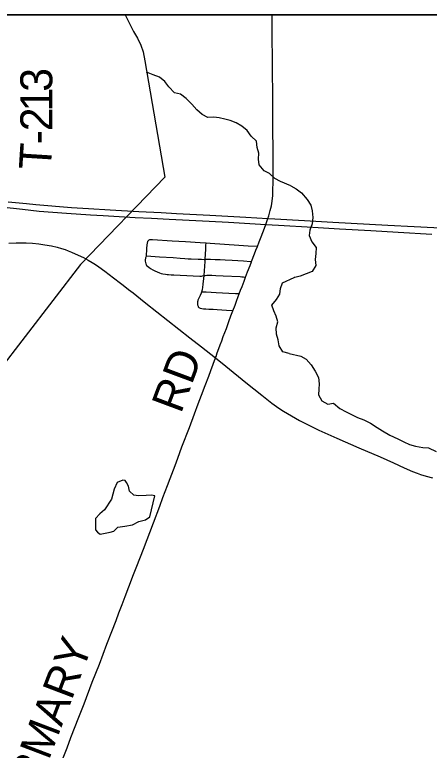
# Model space of a CAD drawing. Extents: x 0 to 34, y 0 to 22.
# Drawn here: x 7.094 to 7.83, y 19.311 to 20.617 of the extents above; entities that cross this region are included whole.
import ezdxf

# ---------------------------------------------------------------- set-up
doc = ezdxf.new("R2010")
doc.units = 0
for name, color, linetype in [('GM_X_Corporation', 7, 'Continuous'), ('GM_X_County_Road', 7, 'Continuous'), ('GM_X_County_Road_Text', 7, 'Continuous'), ('GM_X_Interstate_Route', 7, 'Continuous'), ('GM_X_Minor_Lake', 7, 'Continuous'), ('GM_X_Minor_River', 7, 'Continuous'), ('GM_X_State_Route', 7, 'Continuous'), ('GM_X_Township_Road', 7, 'Continuous'), ('GM_X_Township_Road_Text', 7, 'Continuous'), ('SH_Data', 7, 'Continuous')]:
    doc.layers.add(name, color=color, linetype=linetype)

msp = doc.modelspace()

# ---------------------------------------------------------------- linework, layer by layer
at = {"layer": 'GM_X_Corporation'}
msp.add_lwpolyline([(8.914, 20.6173), (5.0338, 20.6173)], dxfattribs=at)
at = {"layer": 'GM_X_County_Road'}
msp.add_line((7.4506, 20.0077), (7.4509, 20.0086), dxfattribs=at)
for points in [[(7.4816, 20.0915), (7.4854, 20.1014), (7.4881, 20.1088), (7.4912, 20.1169), (7.493, 20.1218), (7.4953, 20.1279), (7.4979, 20.1348), (7.5013, 20.1438), (7.504, 20.151), (7.5077, 20.1606), (7.512, 20.172), (7.5145, 20.1785), (7.5148, 20.1791), (7.5199, 20.1924), (7.5225, 20.1991), (7.5252, 20.2059), (7.5283, 20.2142), (7.5316, 20.2228), (7.5374, 20.2381), (7.5399, 20.2448), (7.5425, 20.2519), (7.5437, 20.2553), (7.5453, 20.2598), (7.5468, 20.2648), (7.548, 20.2693), (7.5491, 20.2739), (7.5499, 20.2778), (7.5508, 20.2819), (7.5514, 20.2862), (7.552, 20.2912), (7.5524, 20.2959), (7.5526, 20.301), (7.5527, 20.3079), (7.5528, 20.3178), (7.5528, 20.3318), (7.5528, 20.3457), (7.5528, 20.3581), (7.5528, 20.369), (7.5528, 20.3876), (7.5527, 20.4033), (7.5525, 20.4283), (7.5524, 20.4691), (7.5519, 20.5238), (7.5517, 20.5451), (7.5515, 20.5708), (7.5513, 20.5927), (7.5511, 20.6173)], [(7.4509, 20.0086), (7.4516, 20.0105), (7.4538, 20.0165), (7.4566, 20.0242), (7.459, 20.0307), (7.4617, 20.0379), (7.4646, 20.0455), (7.47, 20.0602), (7.4745, 20.0723), (7.4782, 20.0825), (7.4816, 20.0915)], [(7.1755, 19.2854), (7.1872, 19.3154), (7.1941, 19.3335), (7.2081, 19.3699), (7.2173, 19.3937), (7.232, 19.4317), (7.2445, 19.4639), (7.258, 19.4994), (7.2665, 19.5216), (7.2742, 19.5417), (7.2793, 19.5551), (7.2851, 19.57), (7.2904, 19.5839), (7.2971, 19.6012), (7.3054, 19.6229), (7.3113, 19.6381), (7.3228, 19.668), (7.3404, 19.7149), (7.3516, 19.7446), (7.3573, 19.7599), (7.3653, 19.7809), (7.3702, 19.7939), (7.3789, 19.8169), (7.3837, 19.8299), (7.3912, 19.8498), (7.4043, 19.8843), (7.4134, 19.9085), (7.4202, 19.9265), (7.4259, 19.9414), (7.4324, 19.9588), (7.4386, 19.9754), (7.4423, 19.9853), (7.4506, 20.0077)]]:
    msp.add_lwpolyline(points, dxfattribs=at)
at = {"layer": 'GM_X_Interstate_Route'}
for points in [[(7.0368, 20.2795), (7.1082, 20.2719), (7.1378, 20.2686), (7.1859, 20.2649), (7.2288, 20.2619), (7.2511, 20.2607), (7.3079, 20.2574), (7.3368, 20.2558), (7.3684, 20.2541), (7.4394, 20.2504), (7.474, 20.2487), (7.5399, 20.2448), (7.5624, 20.2435), (7.6233, 20.24), (7.6706, 20.2372), (7.7266, 20.234), (7.775, 20.2312), (7.8347, 20.2273)], [(7.0827, 20.2852), (7.1151, 20.2817), (7.1318, 20.2802), (7.1533, 20.2783), (7.1738, 20.2767), (7.195, 20.275), (7.2252, 20.2732), (7.2635, 20.2708), (7.3145, 20.2679), (7.3541, 20.2658), (7.3813, 20.2643), (7.4409, 20.261), (7.5047, 20.2575), (7.5437, 20.2553), (7.556, 20.2546), (7.6087, 20.2517), (7.6588, 20.249), (7.7568, 20.2436), (7.8034, 20.241), (7.8612, 20.2379)]]:
    msp.add_lwpolyline(points, dxfattribs=at)
at = {"layer": 'GM_X_Minor_Lake'}
msp.add_line((7.3342, 19.7257), (7.343, 19.7629), dxfattribs=at)
msp.add_lwpolyline([(7.343, 19.7629), (7.3373, 19.764), (7.3275, 19.7636), (7.3139, 19.7627), (7.3059, 19.7638), (7.2983, 19.7713), (7.296, 19.78), (7.2925, 19.7865), (7.2906, 19.7902), (7.2864, 19.7906), (7.2759, 19.7863), (7.271, 19.7749), (7.2659, 19.757), (7.2539, 19.738), (7.2456, 19.7307), (7.2374, 19.7223), (7.2375, 19.7022), (7.241, 19.6981), (7.2459, 19.6947), (7.2637, 19.6982), (7.2701, 19.7002), (7.2776, 19.7071), (7.2897, 19.7091), (7.3033, 19.7114), (7.3146, 19.7172), (7.3263, 19.72), (7.3342, 19.7257)], dxfattribs=at)
at = {"layer": 'GM_X_Minor_River'}
for p, q in [((7.325, 20.5351), (7.3606, 20.3286)), ((7.3606, 20.3286), (7.2112, 20.1735)), ((7.2112, 20.1735), (7.0028, 19.903))]:
    msp.add_line(p, q, dxfattribs=at)
for points in [[(7.2903, 20.6173), (7.2994, 20.5994), (7.3051, 20.5876), (7.3124, 20.5755), (7.3181, 20.5634), (7.3221, 20.5513), (7.325, 20.5351)], [(7.5846, 20.3135), (7.5658, 20.3211), (7.5563, 20.3263), (7.5468, 20.335), (7.5369, 20.3402), (7.5285, 20.3504), (7.5273, 20.361), (7.5276, 20.3712), (7.5249, 20.3815), (7.5237, 20.3925), (7.5141, 20.4015), (7.5072, 20.4117), (7.4973, 20.4192), (7.4875, 20.4252), (7.4768, 20.4293), (7.4673, 20.4319), (7.4575, 20.4344), (7.4476, 20.4351), (7.437, 20.435), (7.4268, 20.4403), (7.4173, 20.4485), (7.4085, 20.4583), (7.3989, 20.4685), (7.3883, 20.4764), (7.378, 20.4786), (7.3681, 20.4891), (7.3605, 20.4989), (7.351, 20.5064), (7.3403, 20.5105), (7.3284, 20.5152)], [(7.5846, 20.3135), (7.5941, 20.308), (7.6036, 20.3012), (7.6132, 20.2892), (7.6202, 20.279), (7.6226, 20.2688), (7.6234, 20.2574), (7.6221, 20.246), (7.6184, 20.2349), (7.617, 20.2254), (7.622, 20.2141), (7.6297, 20.2039), (7.6291, 20.1929), (7.6277, 20.1826), (7.6286, 20.1716), (7.6222, 20.1613), (7.6011, 20.1527), (7.5913, 20.1507), (7.5905, 20.1503)], [(7.5812, 20.0156), (7.5704, 20.0188), (7.5639, 20.029), (7.562, 20.0396), (7.5588, 20.0502), (7.5584, 20.0612), (7.5613, 20.0718), (7.5586, 20.0817), (7.554, 20.0915), (7.5509, 20.1017), (7.5588, 20.1113), (7.5651, 20.1212), (7.5662, 20.1311), (7.5695, 20.1409), (7.5905, 20.1503)], [(7.5812, 20.0156), (7.6019, 20.0111), (7.6119, 20.0055), (7.6207, 19.9953), (7.6276, 19.984), (7.6334, 19.9727), (7.6347, 19.9617), (7.634, 19.9522), (7.6338, 19.9419), (7.6392, 19.9314), (7.6499, 19.9258), (7.6604, 19.9274), (7.6715, 19.9177), (7.6826, 19.9121), (7.7028, 19.9017), (7.7138, 19.8977), (7.7256, 19.8917), (7.7378, 19.8839), (7.7473, 19.8783), (7.7603, 19.8705), (7.7744, 19.8638), (7.7851, 19.8586), (7.7953, 19.8538), (7.806, 19.8513), (7.8185, 19.8484), (7.8287, 19.8478), (7.8424, 19.8418)]]:
    msp.add_lwpolyline(points, dxfattribs=at)
at = {"layer": 'GM_X_State_Route'}
for points in [[(7.0839, 20.2113), (7.097, 20.2122), (7.1063, 20.2123), (7.1145, 20.2121), (7.1257, 20.2113), (7.1368, 20.2102), (7.1479, 20.2087), (7.1596, 20.2066), (7.1694, 20.2043), (7.1772, 20.2022), (7.1837, 20.2001), (7.1891, 20.198), (7.1948, 20.1957), (7.2067, 20.1904), (7.2163, 20.1858), (7.2245, 20.1815), (7.2316, 20.1774), (7.2374, 20.1738), (7.2436, 20.1696), (7.2542, 20.162), (7.2695, 20.1501), (7.2818, 20.1407), (7.2867, 20.1369), (7.2965, 20.1292), (7.3043, 20.1231), (7.3178, 20.1126)], [(7.3178, 20.1126), (7.3273, 20.1052), (7.4053, 20.0432), (7.426, 20.0272), (7.4506, 20.0077), (7.4689, 19.9933), (7.5047, 19.9643), (7.5328, 19.9417), (7.5508, 19.9275), (7.5629, 19.9188), (7.5717, 19.913), (7.5855, 19.9047), (7.5996, 19.8968), (7.6138, 19.8893), (7.6339, 19.8797), (7.6663, 19.8651), (7.705, 19.8482), (7.7433, 19.8319), (7.7666, 19.8215), (7.7858, 19.8126), (7.8005, 19.8062), (7.8085, 19.8028), (7.8144, 19.8008), (7.8245, 19.7977), (7.8359, 19.7947)]]:
    msp.add_lwpolyline(points, dxfattribs=at)
at = {"layer": 'GM_X_Township_Road'}
for points in [[(7.3282, 20.189), (7.3284, 20.1919), (7.3287, 20.1981), (7.329, 20.2028), (7.3294, 20.2081), (7.3295, 20.2098), (7.3297, 20.2111), (7.3298, 20.212), (7.3301, 20.213), (7.3303, 20.2139), (7.3308, 20.2149), (7.3314, 20.2158), (7.3319, 20.2164), (7.3324, 20.2171), (7.3331, 20.2176), (7.334, 20.2181), (7.3346, 20.2182), (7.3353, 20.2183), (7.3363, 20.2182), (7.3386, 20.2181), (7.3738, 20.2159), (7.3976, 20.2144), (7.4236, 20.2128), (7.434, 20.2122), (7.4415, 20.2117), (7.4921, 20.2082), (7.5089, 20.207), (7.5238, 20.206), (7.5252, 20.2059)], [(7.4816, 20.0915), (7.48, 20.0915), (7.4702, 20.092), (7.4534, 20.093), (7.4466, 20.0935), (7.4391, 20.0939), (7.4333, 20.0943), (7.4294, 20.0945), (7.4266, 20.0949), (7.4241, 20.0955), (7.4228, 20.0961), (7.4218, 20.0969), (7.4208, 20.0978), (7.4203, 20.0989), (7.4198, 20.1003), (7.4195, 20.1017), (7.4193, 20.1033), (7.4192, 20.1049), (7.4193, 20.1063), (7.4194, 20.108), (7.4197, 20.1095), (7.4201, 20.1108), (7.4207, 20.1123), (7.4221, 20.1157), (7.4238, 20.119), (7.4257, 20.1231), (7.4267, 20.1254), (7.4275, 20.1291), (7.4282, 20.1331), (7.429, 20.139), (7.43, 20.1488), (7.4304, 20.154), (7.4316, 20.1707), (7.4321, 20.1787), (7.4324, 20.1829), (7.4328, 20.192), (7.4333, 20.2006), (7.4337, 20.2072), (7.434, 20.2122)], [(7.3282, 20.189), (7.3273, 20.1869), (7.3267, 20.1853), (7.3263, 20.184), (7.3261, 20.1825), (7.3261, 20.1814), (7.3261, 20.1795), (7.3263, 20.1774), (7.3269, 20.175), (7.3275, 20.1735), (7.3285, 20.172), (7.33, 20.1706), (7.3322, 20.1689), (7.3353, 20.1668), (7.3397, 20.1644), (7.3433, 20.1625), (7.3474, 20.1604), (7.3513, 20.1589), (7.3543, 20.1579), (7.3575, 20.1571), (7.362, 20.1563), (7.3647, 20.1559), (7.3673, 20.1557), (7.3718, 20.1554), (7.3769, 20.1552), (7.4111, 20.1536), (7.4226, 20.153), (7.4257, 20.153), (7.4278, 20.1533), (7.4304, 20.154), (7.4326, 20.1544), (7.4354, 20.1547), (7.4374, 20.1549), (7.4402, 20.1547), (7.4439, 20.1546), (7.4511, 20.1543), (7.4642, 20.1538), (7.4945, 20.1521), (7.4975, 20.1518), (7.5004, 20.1515), (7.5032, 20.1512), (7.504, 20.151)], [(7.3282, 20.189), (7.3361, 20.1885), (7.3513, 20.1874), (7.3756, 20.1858), (7.3878, 20.1849), (7.396, 20.1843), (7.4022, 20.184), (7.4076, 20.1837), (7.4199, 20.1831), (7.426, 20.1829), (7.4306, 20.1828), (7.4324, 20.1829), (7.4352, 20.183), (7.442, 20.183), (7.4504, 20.1827), (7.4592, 20.1823), (7.4678, 20.1818), (7.4803, 20.1811), (7.5006, 20.18), (7.513, 20.1792), (7.5148, 20.1791)], [(7.4267, 20.1254), (7.4339, 20.125), (7.4518, 20.124), (7.4742, 20.1228), (7.4864, 20.1222), (7.4915, 20.1219), (7.493, 20.1218)]]:
    msp.add_lwpolyline(points, dxfattribs=at)
at = {"layer": 'SH_Data'}
msp.add_line((2.114, 20.6173), (8.914, 20.6173), dxfattribs=at)

# ---------------------------------------------------------------- texts
at = {"layer": 'GM_X_County_Road_Text'}
for s, rotation, p in [('RD', 69.5588, (7.3892, 19.9073)), ('INFIRMARY', 69.1728, (7.0842, 19.1066))]:
    msp.add_text(s, height=0.05682, rotation=rotation, dxfattribs=at).set_placement(p)
at = {"layer": 'GM_X_Township_Road_Text'}
for s, rotation, p in [('3', 89.9991, (7.161, 20.4804)), ('1', 89.9811, (7.161, 20.4454)), ('2', 89.9323, (7.161, 20.4103)), ('-', 89.9682, (7.161, 20.387)), ('T', 86.4277, (7.1582, 20.3407))]:
    msp.add_text(s, height=0.0568, rotation=rotation, dxfattribs=at).set_placement(p)

doc.saveas('drawing.dxf')
